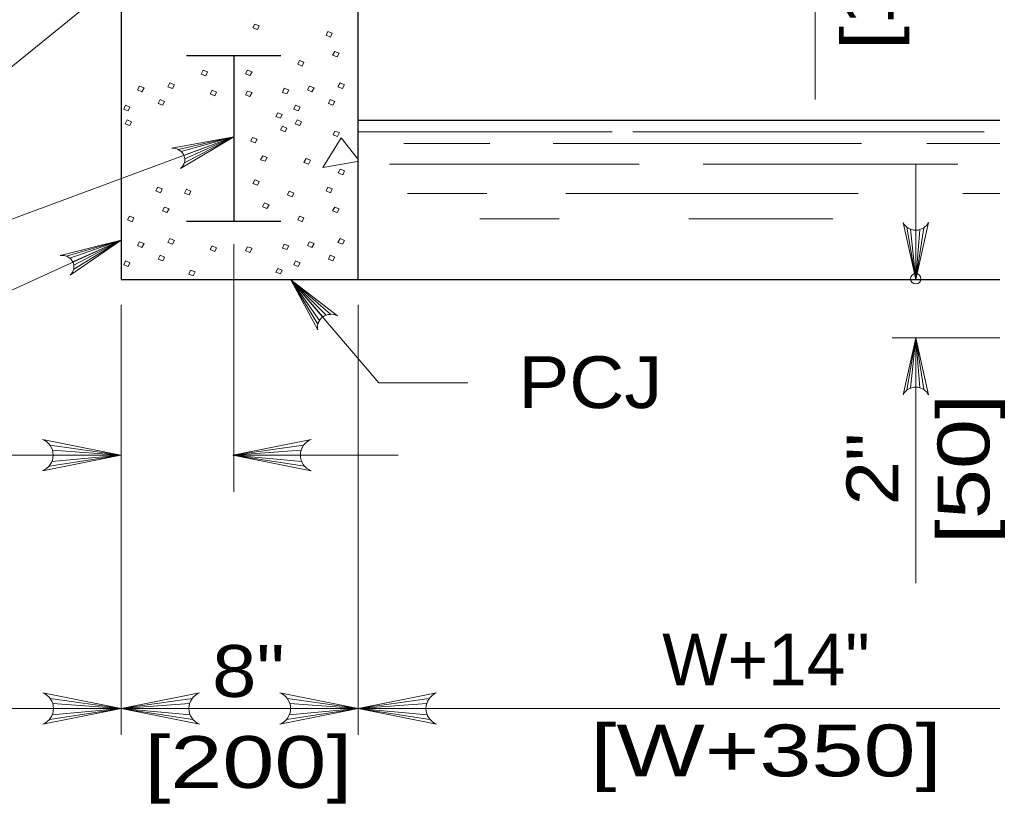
# Model space of a CAD drawing. Extents: x 1083.1 to 1123, y 697.4 to 741.4.
# Drawn here: x 1091.119 to 1094.048, y 701.401 to 703.761 of the extents above; entities that cross this region are included whole.
import ezdxf
from ezdxf.enums import TextEntityAlignment as Align

# ---------------------------------------------------------------- set-up
doc = ezdxf.new("R2010")
doc.units = 0
doc.header["$LTSCALE"] = 0.062
doc.header["$PDMODE"] = 32
doc.header["$PDSIZE"] = 0.031
doc.layers.add('1', color=7, linetype='Continuous', lineweight=13)

msp = doc.modelspace()

# ---------------------------------------------------------------- linework, layer by layer
at = {"layer": '1'}
for p, q in [((1093.514, 704.37917), (1093.514, 703.5205)), ((1091.76367, 703.50533), (1091.76367, 703.154)), ((1091.59617, 703.37017), (1091.76367, 703.4075)), ((1091.606, 703.36333), (1091.76367, 703.4075)), ((1091.614, 703.35175), (1091.76367, 703.4075)), ((1091.61525, 703.32967), (1091.76367, 703.4075)), ((1091.61658, 703.34133), (1091.76367, 703.4075)), ((1092.13517, 703.34367), (1092.08733, 703.40517)), ((1092.13858, 703.42283), (1092.90283, 703.42283)), ((1092.96467, 703.42283), (1094.02267, 703.42283)), ((1092.27583, 703.38742), (1092.53425, 703.38742)), ((1092.72533, 703.38742), (1093.65308, 703.38742)), ((1093.84958, 703.38742), (1094.45983, 703.38742)), ((1092.23292, 703.32575), (1092.9845, 703.32575)), ((1093.17667, 703.32575), (1093.94325, 703.32575)), ((1093.81633, 703.32592), (1093.81633, 702.98067)), ((1092.28692, 703.23683), (1092.526, 703.23683)), ((1092.76317, 703.23683), (1093.6435, 703.23683)), ((1093.95833, 703.23683), (1094.29858, 703.23683)), ((1092.50442, 703.16125), (1092.74358, 703.16125)), ((1093.13308, 703.16125), (1093.56692, 703.16125)), ((1093.78967, 703.13558), (1093.81633, 702.97825)), ((1093.8405, 703.13375), (1093.81633, 702.97825)), ((1093.80083, 703.12967), (1093.81633, 702.97825)), ((1093.82858, 703.1285), (1093.81633, 702.97825)), ((1093.81633, 703.12683), (1093.81633, 702.97825)), ((1091.2605, 703.04833), (1091.42492, 703.09717)), ((1091.27075, 703.04225), (1091.42492, 703.09717)), ((1091.2795, 703.03125), (1091.42492, 703.09717)), ((1091.28233, 703.00933), (1091.42492, 703.09717)), ((1091.28275, 703.021), (1091.42492, 703.09717)), ((1091.76367, 703.085), (1091.76367, 702.33883)), ((1092.03183, 702.8655), (1091.9355, 702.97775)), ((1092.02167, 702.85483), (1091.9355, 702.97775)), ((1092.01683, 702.84417), (1091.9355, 702.97775)), ((1092.04233, 702.871), (1091.9355, 702.97775)), ((1092.05492, 702.87358), (1091.9355, 702.97775)), ((1091.42492, 702.90208), (1091.42492, 701.60733)), ((1092.13858, 702.90208), (1092.13858, 701.60733)), ((1091.42492, 702.82633), (1091.42492, 702.76292)), ((1094.37558, 702.80275), (1093.74558, 702.80275)), ((1093.78967, 702.64542), (1093.81633, 702.80275)), ((1093.80083, 702.65133), (1093.81633, 702.80275)), ((1093.81633, 702.80275), (1093.81633, 702.06408)), ((1093.81633, 702.65408), (1093.81633, 702.80275)), ((1093.82858, 702.6525), (1093.81633, 702.80275)), ((1093.8405, 702.64725), (1093.81633, 702.80275)), ((1091.21067, 702.47958), (1091.42392, 702.44975)), ((1091.21783, 702.46483), (1091.42392, 702.44975)), ((1091.97408, 702.47958), (1091.76083, 702.44975)), ((1091.96692, 702.46483), (1091.76083, 702.44975)), ((1090.5105, 702.44975), (1091.42392, 702.44975)), ((1091.20808, 702.41675), (1091.42392, 702.44975)), ((1091.21625, 702.43058), (1091.42392, 702.44975)), ((1091.22008, 702.44975), (1091.42392, 702.44975)), ((1091.42383, 702.44975), (1091.42392, 702.44975)), ((1091.76083, 702.44975), (1092.259, 702.44975)), ((1091.96467, 702.44975), (1091.76083, 702.44975)), ((1091.96842, 702.43058), (1091.76083, 702.44975)), ((1091.97658, 702.41675), (1091.76083, 702.44975)), ((1091.21167, 701.71675), (1091.42492, 701.68692)), ((1091.21892, 701.702), (1091.42492, 701.68692)), ((1091.63825, 701.71675), (1091.42492, 701.68692)), ((1091.631, 701.702), (1091.42492, 701.68692)), ((1091.92533, 701.71675), (1092.13858, 701.68692)), ((1091.9325, 701.702), (1092.13858, 701.68692)), ((1092.35192, 701.71675), (1092.13858, 701.68692)), ((1092.34467, 701.702), (1092.13858, 701.68692)), ((1091.42492, 701.68692), (1090.56375, 701.68692)), ((1091.20917, 701.65392), (1091.42492, 701.68692)), ((1091.21733, 701.66775), (1091.42492, 701.68692)), ((1091.22108, 701.68692), (1091.42492, 701.68692)), ((1092.13858, 701.68692), (1091.42492, 701.68692)), ((1091.62883, 701.68692), (1091.42492, 701.68692)), ((1091.63258, 701.66775), (1091.42492, 701.68692)), ((1091.64075, 701.65392), (1091.42492, 701.68692)), ((1091.92283, 701.65392), (1092.13858, 701.68692)), ((1091.931, 701.66775), (1092.13858, 701.68692)), ((1091.93475, 701.68692), (1092.13858, 701.68692)), ((1092.3425, 701.68692), (1092.13858, 701.68692)), ((1092.34625, 701.66775), (1092.13858, 701.68692)), ((1092.35442, 701.65392), (1092.13858, 701.68692))]:
    msp.add_line(p, q, dxfattribs=at)
at = {"layer": '1', "lineweight": 25}
for p, q in [((1092.13858, 702.97792), (1092.13858, 704.10533)), ((1091.42492, 703.97992), (1091.42492, 702.97792)), ((1091.62158, 703.6525), (1091.90567, 703.6525)), ((1091.76367, 703.6525), (1091.76367, 703.154)), ((1092.13858, 703.45842), (1094.45983, 703.45842)), ((1091.62158, 703.154), (1091.90567, 703.154))]:
    msp.add_line(p, q, dxfattribs=at)
at = {"layer": '1'}
for points in [[(1091.53892, 703.97992), (1090.60408, 703.22075), (1090.33183, 703.22075)], [(1091.76367, 703.4075), (1090.32617, 702.87517), (1087.73908, 702.87517)], [(1091.57783, 703.374), (1091.76367, 703.4075), (1091.60367, 703.31225)], [(1092.08733, 703.40517), (1092.03167, 703.3155), (1092.13608, 703.33383)], [(1093.77817, 703.15), (1093.81633, 702.97825), (1093.8545, 703.15)], [(1091.42492, 703.09717), (1089.95692, 702.42633), (1089.69267, 702.42633)], [(1091.24183, 703.05092), (1091.42492, 703.09717), (1091.27192, 702.99108)], [(1092.01733, 702.82692), (1091.9355, 702.97775), (1092.07633, 702.86908)], [(1091.9355, 702.97775), (1092.20075, 702.6675), (1092.46825, 702.6675)], [(1093.77817, 702.631), (1093.81633, 702.80275), (1093.8545, 702.631)], [(1091.18833, 702.40258), (1091.42392, 702.44975), (1091.18833, 702.49683)], [(1091.99642, 702.40258), (1091.76083, 702.44975), (1091.99642, 702.49683)], [(1091.18933, 701.63975), (1091.42492, 701.68692), (1091.18933, 701.734)], [(1091.6605, 701.63975), (1091.42492, 701.68692), (1091.6605, 701.734)], [(1091.903, 701.63975), (1092.13858, 701.68692), (1091.903, 701.734)], [(1092.37417, 701.63975), (1092.13858, 701.68692), (1092.37417, 701.734)], [(1092.13858, 701.68692), (1093.89508, 701.68692), (1094.45983, 701.68692)]]:
    msp.add_lwpolyline(points, dxfattribs=at)
for points in [[(1091.82692, 703.747), (1091.84033, 703.74217), (1091.835, 703.73083), (1091.8215, 703.73567)], [(1092.04692, 703.72517), (1092.06042, 703.72033), (1092.055, 703.70825), (1092.0415, 703.71383)], [(1092.06758, 703.66458), (1092.081, 703.65975), (1092.07475, 703.64842), (1092.06125, 703.65325)], [(1091.96158, 703.63792), (1091.97508, 703.63308), (1091.96967, 703.62092), (1091.95625, 703.62658)], [(1091.6715, 703.60883), (1091.685, 703.60317), (1091.67967, 703.59183), (1091.66617, 703.59667)], [(1091.80533, 703.60883), (1091.81883, 703.60392), (1091.8125, 703.59267), (1091.79908, 703.5975)], [(1091.48025, 703.56033), (1091.49375, 703.5555), (1091.48742, 703.54333), (1091.474, 703.549)], [(1091.57183, 703.57), (1091.58533, 703.56433), (1091.57908, 703.55308), (1091.56558, 703.55867)], [(1091.6985, 703.54817), (1091.712, 703.54258), (1091.70658, 703.53125), (1091.69308, 703.53692)], [(1091.80533, 703.54575), (1091.81883, 703.54092), (1091.8125, 703.52883), (1091.79908, 703.5345)], [(1091.91583, 703.55383), (1091.92925, 703.54817), (1091.92392, 703.53692), (1091.91042, 703.54175)], [(1091.99217, 703.56033), (1092.00558, 703.5555), (1091.99933, 703.54333), (1091.98583, 703.549)], [(1092.08375, 703.57), (1092.09717, 703.56433), (1092.09092, 703.55308), (1092.07742, 703.55867)], [(1091.54225, 703.51992), (1091.55567, 703.51425), (1091.55033, 703.50292), (1091.53683, 703.50858)], [(1092.05408, 703.51992), (1092.06758, 703.51425), (1092.06217, 703.50292), (1092.04867, 703.50858)], [(1091.43808, 703.50292), (1091.4515, 703.49725), (1091.44617, 703.486), (1091.43267, 703.49083)], [(1091.94992, 703.50292), (1091.96342, 703.49725), (1091.958, 703.486), (1091.9445, 703.49083)], [(1091.44258, 703.4585), (1091.456, 703.45283), (1091.45067, 703.4415), (1091.43717, 703.44717)], [(1091.89608, 703.48033), (1091.9095, 703.4755), (1091.90408, 703.46417), (1091.89067, 703.469)], [(1091.95442, 703.4585), (1091.96792, 703.45283), (1091.9625, 703.4415), (1091.949, 703.44717)], [(1091.91042, 703.43992), (1091.92392, 703.43425), (1091.9185, 703.42292), (1091.905, 703.42858)], [(1091.82058, 703.406), (1091.83408, 703.40117), (1091.82867, 703.38983), (1091.81525, 703.39467)], [(1092.06842, 703.42533), (1092.08192, 703.4205), (1092.07658, 703.40842), (1092.06308, 703.41408)], [(1091.85117, 703.35025), (1091.86458, 703.34533), (1091.85833, 703.33408), (1091.84483, 703.33892)], [(1091.98133, 703.34217), (1091.99483, 703.33725), (1091.9885, 703.326), (1091.97508, 703.33083)], [(1092.08375, 703.31058), (1092.09717, 703.30575), (1092.09183, 703.29367), (1092.07833, 703.29933)], [(1091.53508, 703.2565), (1091.5485, 703.25158), (1091.54317, 703.2395), (1091.52967, 703.24517)], [(1091.82692, 703.27833), (1091.84033, 703.27342), (1091.835, 703.26217), (1091.8215, 703.267)], [(1092.04692, 703.2565), (1092.06042, 703.25158), (1092.055, 703.2395), (1092.0415, 703.24517)], [(1091.62125, 703.25), (1091.63475, 703.24433), (1091.62933, 703.233), (1091.61583, 703.23792)], [(1091.93108, 703.24433), (1091.9445, 703.23867), (1091.93917, 703.22742), (1091.92567, 703.233)], [(1091.55567, 703.19583), (1091.56917, 703.191), (1091.56292, 703.17967), (1091.54942, 703.18458)], [(1091.8565, 703.20875), (1091.87, 703.20317), (1091.86375, 703.19183), (1091.85025, 703.19667)], [(1092.06758, 703.19583), (1092.081, 703.191), (1092.07475, 703.17967), (1092.06125, 703.18458)], [(1091.44975, 703.16917), (1091.46325, 703.16433), (1091.45783, 703.15225), (1091.44433, 703.15792)], [(1091.96158, 703.16917), (1091.97508, 703.16433), (1091.96967, 703.15225), (1091.95625, 703.15792)], [(1091.48025, 703.09158), (1091.49375, 703.08675), (1091.48742, 703.07467), (1091.474, 703.08033)], [(1091.57183, 703.10133), (1091.58533, 703.09567), (1091.57908, 703.08433), (1091.56558, 703.09)], [(1091.6985, 703.0795), (1091.712, 703.07383), (1091.70658, 703.0625), (1091.69308, 703.06817)], [(1091.80533, 703.07708), (1091.81883, 703.07225), (1091.8125, 703.06008), (1091.79908, 703.06575)], [(1091.91583, 703.08517), (1091.92925, 703.0795), (1091.92392, 703.06817), (1091.91042, 703.073)], [(1091.99217, 703.09158), (1092.00558, 703.08675), (1091.99933, 703.07467), (1091.98583, 703.08033)], [(1092.08375, 703.10133), (1092.09717, 703.09567), (1092.09092, 703.08433), (1092.07742, 703.09)], [(1091.54225, 703.05125), (1091.55567, 703.04558), (1091.55033, 703.03425), (1091.53683, 703.03992)], [(1092.05408, 703.05125), (1092.06758, 703.04558), (1092.06217, 703.03425), (1092.04867, 703.03992)], [(1091.43808, 703.03425), (1091.4515, 703.02858), (1091.44617, 703.01725), (1091.43267, 703.02208)], [(1091.94992, 703.03425), (1091.96342, 703.02858), (1091.958, 703.01725), (1091.9445, 703.02208)], [(1091.63383, 703.00675), (1091.64733, 703.00108), (1091.64192, 702.98983), (1091.62842, 702.99467)], [(1091.89608, 703.01158), (1091.9095, 703.00675), (1091.90408, 702.99542), (1091.89067, 703.00033)]]:
    msp.add_lwpolyline(points, close=True, dxfattribs=at)
at = {"layer": '1', "lineweight": 25}
msp.add_lwpolyline([(1091.42492, 702.97792), (1092.13858, 702.97792), (1095.16083, 702.97792)], dxfattribs=at)
at = {"layer": '1'}
for centre, start, end in [((1091.1693, 702.44978), 292.08605, 67.91218), ((1092.01543, 702.44977), 112.08782, 247.91395), ((1091.17035, 701.68694), 292.08605, 67.91218), ((1091.67957, 701.68694), 112.08782, 247.91395), ((1091.88399, 701.68694), 292.08605, 67.91218), ((1092.39321, 701.68694), 112.08782, 247.91395)]:
    msp.add_arc(centre, 0.05085, start, end, dxfattribs=at)
for centre, major_axis, ratio, start_param, end_param in [((1091.57668, 703.33791), (0.03934, 0.00709), 0.899905, 5.2950757, 7.6656889), ((1093.81641, 703.16388), (0.04119, 0), 0.9, 3.5270669, 5.8976801), ((1091.24322, 703.01485), (0.03876, 0.00979), 0.899905, 5.2950757, 7.6656889), ((1092.05585, 702.83747), (0.03938, 0.0069), 0.899905, 0.8762993, 3.2469125), ((1093.81641, 702.61711), (0.04119, 0), 0.9, 0.3855052, 2.7561184)]:
    msp.add_ellipse(centre, major_axis=major_axis, ratio=ratio, start_param=start_param, end_param=end_param, dxfattribs=at)
msp.add_point((1093.81633, 702.98067), dxfattribs=at)

# ---------------------------------------------------------------- texts
for s, width, p in [('[100]', 1.25, (1093.74967, 703.95875)), ('[50]', 1.3, (1094.03808, 702.40771)), ('2"', 1.15, (1093.76408, 702.40771))]:
    msp.add_text(s, height=0.156, rotation=90, dxfattribs=dict(at, width=width)).set_placement(p, align=Align.CENTER)
at = {"layer": '1', "width": 1.1}
msp.add_text('PCJ', height=0.156, dxfattribs=at).set_placement((1092.62058, 702.59117))
at = {"layer": '1'}
msp.add_text('W+14"', height=0.156, dxfattribs=at).set_placement((1093.36575, 701.75658), align=Align.CENTER)
for s, width, p in [('8"', 1.15, (1091.80792, 701.72183)), ('[W+350]', 1.35, (1093.36575, 701.48258)), ('[200]', 1.35, (1091.80792, 701.44783))]:
    msp.add_text(s, height=0.156, dxfattribs=dict(at, width=width)).set_placement(p, align=Align.CENTER)

doc.saveas('drawing.dxf')
